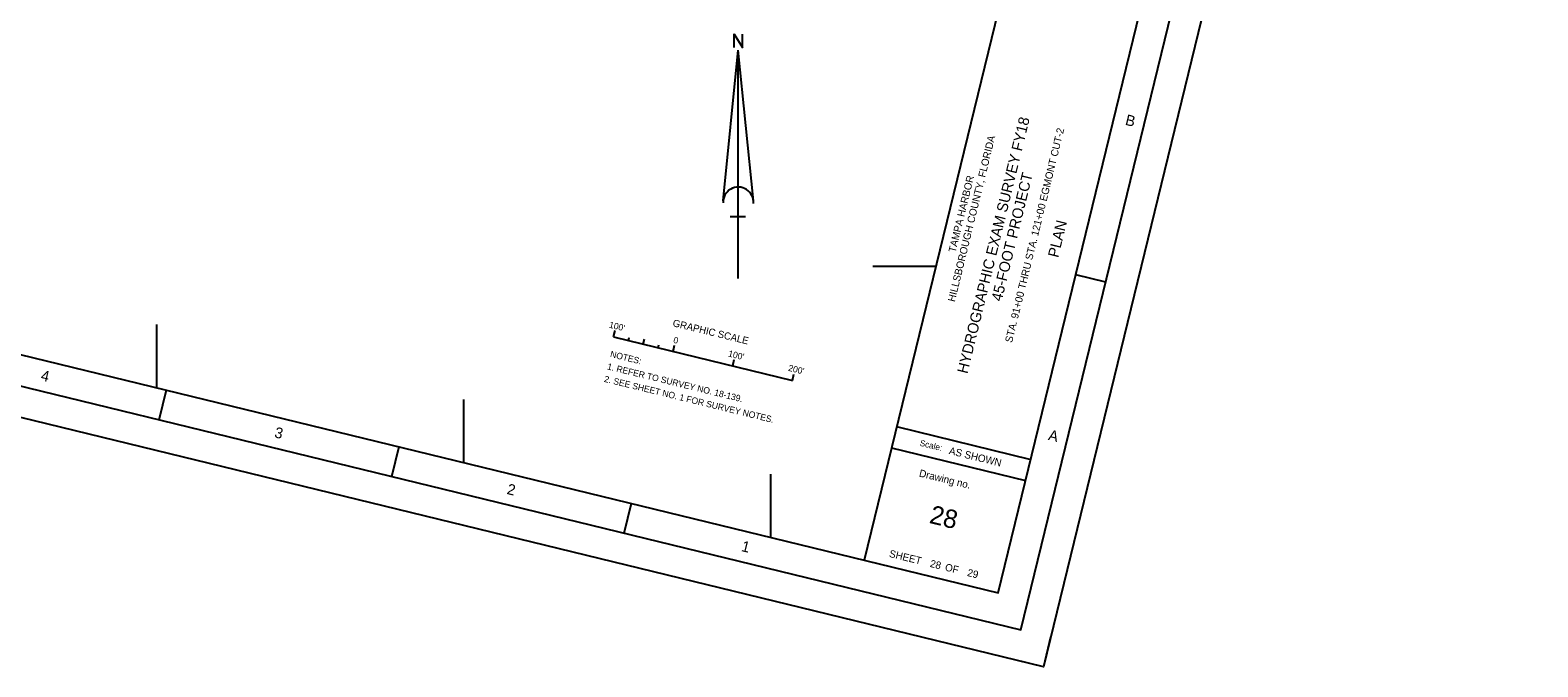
# Model space of a CAD drawing. Extents: x 412170 to 417250, y 1187847 to 1192192.
# Drawn here: x 414793 to 417250, y 1187847 to 1188884 of the extents above; entities that cross this region are included whole.
import ezdxf

# ---------------------------------------------------------------- set-up
doc = ezdxf.new("R2010")
doc.units = 0
for name, color, linetype in [('G-ANNO-NPLT', 7, 'Continuous'), ('G-ANNO-TEXT-DRWG', 7, 'Continuous'), ('G-ANNO-TEXT-PROJ', 7, 'Continuous'), ('G-ANNO-TEXT-TTLB', 7, 'Continuous'), ('G-ANNO-TTLB', 7, 'Continuous'), ('V-ANNO-NOTE', 7, 'Continuous'), ('V-ANNO-SYMB', 7, 'Continuous'), ('V-TOPO-COOR-STAT', 7, 'Continuous')]:
    doc.layers.add(name, color=color, linetype=linetype)

msp = doc.modelspace()

# ---------------------------------------------------------------- linework, layer by layer
at = {"layer": 'G-ANNO-NPLT'}
msp.add_lwpolyline([(412975.1, 1192192.3), (417249.8, 1191149.8), (416444.2, 1187846.7), (412169.5, 1188889.2)], close=True, dxfattribs=at)
msp.add_lwpolyline([(416456, 1187895.2), (416444.2, 1187846.7), (416395.6, 1187858.5)], dxfattribs=at)
at = {"layer": 'G-ANNO-TTLB'}
for p, q in [((416910.3, 1191129.7), (416152.1, 1188020.8)), ((416545.7, 1188473.8), (416497.1, 1188485.6)), ((415003.6, 1188249.4), (415015.5, 1188298)), ((416205.1, 1188238.2), (416423.8, 1188184.9)), ((415382.5, 1188157), (415394.4, 1188205.6)), ((416196.7, 1188203.5), (416415.3, 1188150.2)), ((415761.4, 1188064.6), (415773.3, 1188113.2))]:
    msp.add_line(p, q, dxfattribs=at)
for points in [[(412229.9, 1188925.9), (416407.5, 1187907.1), (417189.3, 1191113.1), (413011.8, 1192131.9)], [(417128.9, 1191076.4), (413121.4, 1192053.7), (412363.2, 1188944.8), (416370.7, 1187967.5)]]:
    msp.add_lwpolyline(points, close=True, dxfattribs=at)
at = {"layer": 'V-ANNO-NOTE'}
for p, q in [((415743.8, 1188384.6), (415746.3, 1188394.8)), ((415743.8, 1188384.6), (416035.2, 1188313.5)), ((415768.1, 1188378.7), (415769.2, 1188383.3)), ((415792.4, 1188372.8), (415794.4, 1188381)), ((415816.7, 1188366.8), (415817.8, 1188371.5)), ((415840.9, 1188360.9), (415843.4, 1188371.1)), ((415840.9, 1188360.9), (415843.4, 1188371.1)), ((415840.9, 1188360.9), (415842.1, 1188365.8)), ((415938.1, 1188337.2), (415940.6, 1188347.4)), ((416035.2, 1188313.5), (416037.7, 1188323.7))]:
    msp.add_line(p, q, dxfattribs=at)
at = {"layer": 'V-ANNO-SYMB'}
for p, q in [((415922.4, 1188606.3), (415947.1, 1188852)), ((415947.1, 1188479.7), (415947.1, 1188852)), ((415971.8, 1188606.3), (415947.1, 1188852)), ((415958.8, 1188580.2), (415934, 1188580.2))]:
    msp.add_line(p, q, dxfattribs=at)
msp.add_lwpolyline([(415940.2, 1188856), (415940.2, 1188877.7), (415953.7, 1188856), (415953.7, 1188877.7)], dxfattribs=at)
msp.add_arc((415947.1, 1188603.8), 24.8, 355.2984, 182.0673, dxfattribs=at)
at = {"layer": 'V-TOPO-COOR-STAT'}
for p, q in [((416166.1, 1188500), (416269, 1188500)), ((415000, 1188301.5), (415000, 1188404.5)), ((415500, 1188179.6), (415500, 1188282.5)), ((416000, 1188057.7), (416000, 1188160.6))]:
    msp.add_line(p, q, dxfattribs=at)

# ---------------------------------------------------------------- texts
at = {"layer": 'G-ANNO-TEXT-DRWG'}
for s, height, rotation, p in [('STA. 91+00 THRU STA. 121+00 EGMONT CUT-2', 12, 76.2946, (416393.1, 1188374.2)), ('PLAN', 17.5, 76.2946, (416468.3, 1188512.7)), ('28', 30, 346.2946, (416256.9, 1188081.5)), (' 28          29', 12, 346.2946, (416254.2, 1188010.8))]:
    msp.add_text(s, height=height, rotation=rotation, dxfattribs=at).set_placement(p)
at = {"layer": 'G-ANNO-TEXT-PROJ'}
for s, height, p in [('HYDROGRAPHIC EXAM SURVEY FY18', 17.5, (416320.4, 1188323.5)), ('HILLSBOROUGH COUNTY, FLORIDA', 12, (416299.9, 1188440.8)), ('TAMPA HARBOR', 12, (416301, 1188521.2)), ('45-FOOT PROJECT', 17.5, (416376.1, 1188441.3))]:
    msp.add_text(s, height=height, rotation=76.2946, dxfattribs=at).set_placement(p)
at = {"layer": 'G-ANNO-TEXT-TTLB'}
for s, height, p in [('Scale:', 10, (416242, 1188207.2)), ('AS SHOWN', 12, (416289.5, 1188193.7)), ('Drawing no.', 12, (416240.8, 1188157.1)), ('SHEET         OF', 12, (416192, 1188026))]:
    msp.add_text(s, height=height, rotation=346.2946, dxfattribs=at).set_placement(p)
at = {"layer": 'G-ANNO-TTLB'}
for s, p in [('B', (416576.4, 1188730.4)), ('4', (414809.7, 1188313.9)), ('3', (415190.4, 1188221)), ('A', (416451.1, 1188216.7)), ('2', (415569, 1188128.7)), ('1', (415951, 1188035.6))]:
    msp.add_text(s, height=17.5, rotation=346.2946, dxfattribs=at).set_placement(p)
at = {"layer": 'V-ANNO-NOTE'}
for s, height, p in [("100'", 10.42, (415735.8, 1188399.7)), ('GRAPHIC SCALE', 11.666, (415839.4, 1188402)), ('0', 10.4, (415840.5, 1188374.8)), ('1. REFER TO SURVEY NO. 18-139.', 10.416, (415732.7, 1188331.7)), ('NOTES:', 10.42, (415737.6, 1188351.9)), ("100'", 10.42, (415929.9, 1188352.7)), ('2. SEE SHEET NO. 1 FOR SURVEY NOTES.', 10.416, (415727.7, 1188311.4)), ("200'", 10.42, (416027.7, 1188329.4))]:
    msp.add_text(s, height=height, rotation=346.2946, dxfattribs=at).set_placement(p)

doc.saveas('drawing.dxf')
